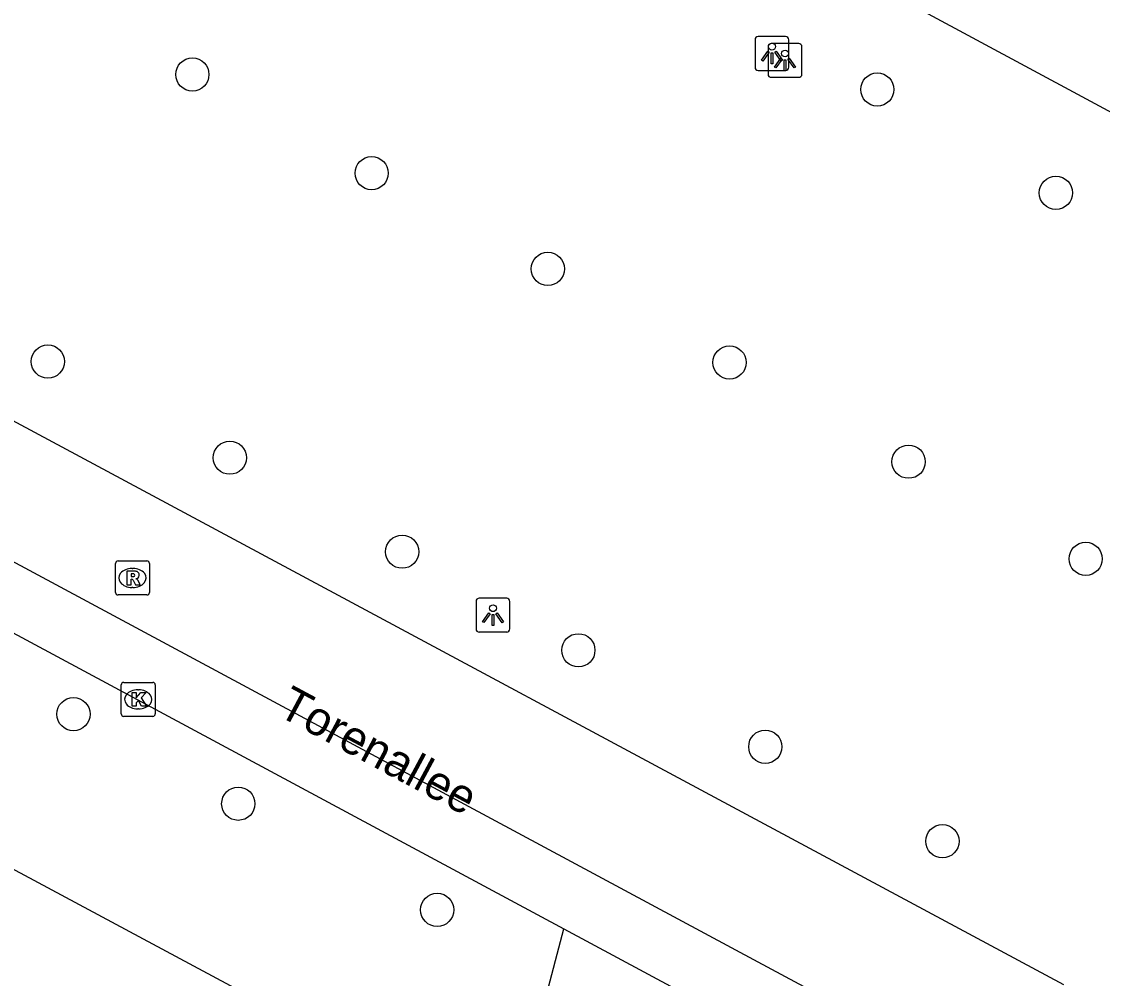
# Model space of a CAD drawing. Extents: x 159489 to 160304, y 383826 to 384530.
# Drawn here: x 159824.86 to 159856.68, y 384144.76 to 384172.94 of the extents above; entities that cross this region are included whole.
import ezdxf

# ---------------------------------------------------------------- set-up
doc = ezdxf.new("R2010")
doc.units = 0
for name, color, linetype in [('IMGEO_Boom', 7, 'Continuous'), ('IMGEO_Kolk', 7, 'Continuous'), ('IMGEO_Lichtpunt', 7, 'Continuous'), ('IMGEO_Openbare_ruimte_label', 7, 'Continuous'), ('IMGEO_Pand', 7, 'Continuous'), ('IMGEO_Rijbaan_lokaal_gesloten', 7, 'Continuous'), ('IMGEO_Rioolput', 7, 'Continuous'), ('IMGEO_Voetgangersgebied_gesloten', 7, 'Continuous'), ('IMGEO_Voetpad_open', 7, 'Continuous')]:
    doc.layers.add(name, color=color, linetype=linetype)

msp = doc.modelspace()

# ---------------------------------------------------------------- linework, layer by layer
at = {"layer": 'IMGEO_Boom'}
for centre in [(159829.887, 384171.386), (159850.05, 384170.943), (159835.164, 384168.48), (159855.308, 384167.898), (159840.349, 384165.658), (159825.633, 384162.929), (159845.701, 384162.903), (159830.989, 384160.097), (159850.971, 384159.979), (159836.063, 384157.328), (159856.184, 384157.117), (159841.25, 384154.425), (159826.385, 384152.545), (159846.752, 384151.583), (159831.238, 384149.905), (159851.966, 384148.8), (159837.094, 384146.777)]:
    msp.add_circle(centre, 0.489, dxfattribs=at)
at = {"layer": 'IMGEO_Kolk'}
for p, q in [((159827.792, 384152.553), (159827.792, 384153.405)), ((159827.867, 384153.479), (159828.719, 384153.479)), ((159828.28, 384153.259), (159828.305, 384153.259)), ((159828.793, 384153.405), (159828.793, 384152.553)), ((159828.303, 384152.699), (159828.278, 384152.699)), ((159828.719, 384152.479), (159827.867, 384152.479))]:
    msp.add_line(p, q, dxfattribs=at)
for points in [[(159827.792, 384152.553), (159827.792, 384153.405)], [(159827.867, 384153.479), (159828.719, 384153.479)], [(159828.793, 384153.405), (159828.793, 384152.553)], [(159828.113, 384153.179), (159828.236, 384153.179), (159828.236, 384153.028), (159828.366, 384153.179), (159828.53, 384153.179), (159828.384, 384153.028), (159828.537, 384152.779), (159828.385, 384152.779), (159828.3, 384152.943), (159828.236, 384152.876), (159828.236, 384152.779), (159828.113, 384152.779), (159828.113, 384153.179)], [(159828.719, 384152.479), (159827.867, 384152.479)]]:
    msp.add_lwpolyline(points, dxfattribs=at)
for centre, start, end in [((159827.869, 384153.403), 91.552, 178.448), ((159827.869, 384153.403), 91.552, 178.448), ((159828.717, 384153.403), 1.552, 88.448), ((159828.717, 384153.403), 1.552, 88.448), ((159827.869, 384152.555), 181.552, 268.448), ((159827.869, 384152.555), 181.552, 268.448), ((159828.717, 384152.555), 271.552, 358.448), ((159828.717, 384152.555), 271.552, 358.448)]:
    msp.add_arc(centre, 0.0765, start, end, dxfattribs=at)
for centre, major_axis, ratio, start_param, end_param in [((159828.279, 384152.979), (-0.387, 0.002), 0.722429, 4.712389, 7.853982), ((159828.304, 384152.979), (-0.39, 0.002), 0.717154, 1.570796, 4.712389)]:
    msp.add_ellipse(centre, major_axis=major_axis, ratio=ratio, start_param=start_param, end_param=end_param, dxfattribs=at)
at = {"layer": 'IMGEO_Lichtpunt'}
for p, q in [((159846.45, 384172.408), (159846.45, 384171.601)), ((159846.45, 384172.408), (159846.45, 384171.601)), ((159847.352, 384172.503), (159846.544, 384172.503)), ((159847.352, 384172.503), (159846.544, 384172.503)), ((159847.736, 384172.299), (159846.928, 384172.299)), ((159847.736, 384172.299), (159846.928, 384172.299)), ((159847.446, 384171.601), (159847.446, 384172.408)), ((159847.446, 384171.601), (159847.446, 384172.408)), ((159846.834, 384172.204), (159846.834, 384171.397)), ((159846.834, 384172.204), (159846.834, 384171.397)), ((159847.83, 384171.397), (159847.83, 384172.204)), ((159847.83, 384171.397), (159847.83, 384172.204)), ((159846.544, 384171.507), (159847.352, 384171.507)), ((159846.544, 384171.507), (159847.352, 384171.507)), ((159846.928, 384171.303), (159847.736, 384171.303)), ((159846.928, 384171.303), (159847.736, 384171.303)), ((159838.238, 384155.865), (159838.238, 384155.058)), ((159838.238, 384155.865), (159838.238, 384155.058)), ((159839.14, 384155.96), (159838.332, 384155.96)), ((159839.14, 384155.96), (159838.332, 384155.96)), ((159839.234, 384155.058), (159839.234, 384155.865)), ((159839.234, 384155.058), (159839.234, 384155.865)), ((159838.332, 384154.964), (159839.14, 384154.964)), ((159838.332, 384154.964), (159839.14, 384154.964))]:
    msp.add_line(p, q, dxfattribs=at)
for points in [[(159846.824, 384172.072), (159846.863, 384172.044), (159846.675, 384171.782), (159846.637, 384171.809), (159846.824, 384172.072)], [(159846.926, 384172.024), (159846.973, 384172.024), (159846.973, 384171.702), (159846.926, 384171.702), (159846.926, 384172.024)], [(159847.036, 384172.044), (159847.074, 384172.071), (159847.261, 384171.809), (159847.222, 384171.781), (159847.036, 384172.044)], [(159847.208, 384171.868), (159847.247, 384171.84), (159847.059, 384171.578), (159847.021, 384171.605), (159847.208, 384171.868)], [(159847.31, 384171.82), (159847.357, 384171.82), (159847.357, 384171.498), (159847.31, 384171.498), (159847.31, 384171.82)], [(159847.42, 384171.84), (159847.458, 384171.867), (159847.645, 384171.605), (159847.606, 384171.577), (159847.42, 384171.84)], [(159838.612, 384155.529), (159838.651, 384155.501), (159838.463, 384155.239), (159838.425, 384155.266), (159838.612, 384155.529)], [(159838.714, 384155.481), (159838.761, 384155.481), (159838.761, 384155.159), (159838.714, 384155.159), (159838.714, 384155.481)], [(159838.824, 384155.501), (159838.862, 384155.528), (159839.049, 384155.266), (159839.01, 384155.238), (159838.824, 384155.501)]]:
    msp.add_lwpolyline(points, dxfattribs=at)
for centre in [(159846.949, 384172.206), (159847.333, 384172.002), (159838.737, 384155.663)]:
    msp.add_circle(centre, 0.0994, dxfattribs=at)
for centre, start, end in [((159846.544, 384172.408), 90, 180), ((159846.544, 384172.408), 90, 180), ((159846.928, 384172.204), 90, 180), ((159846.928, 384172.204), 90, 180), ((159847.352, 384172.408), 0, 90), ((159847.352, 384172.408), 0, 90), ((159847.736, 384172.204), 0, 90), ((159847.736, 384172.204), 0, 90), ((159846.544, 384171.601), 180, 270), ((159846.544, 384171.601), 180, 270), ((159846.928, 384171.397), 180, 270), ((159846.928, 384171.397), 180, 270), ((159847.352, 384171.601), 270, 0), ((159847.352, 384171.601), 270, 360), ((159847.736, 384171.397), 270, 0), ((159847.736, 384171.397), 270, 360), ((159838.332, 384155.865), 90, 180), ((159838.332, 384155.865), 90, 180), ((159839.14, 384155.865), 0, 90), ((159839.14, 384155.865), 0, 90), ((159838.332, 384155.058), 180, 270), ((159838.332, 384155.058), 180, 270), ((159839.14, 384155.058), 270, 0), ((159839.14, 384155.058), 270, 360)]:
    msp.add_arc(centre, 0.0946, start, end, dxfattribs=at)
at = {"layer": 'IMGEO_Pand'}
msp.add_lwpolyline([(159839.222, 384140.129), (159819.699, 384150.609), (159819.305, 384150.823), (159814.929, 384153.207), (159799.236, 384161.615), (159795.062, 384163.855)], dxfattribs=at)
at = {"layer": 'IMGEO_Rijbaan_lokaal_gesloten'}
for points in [[(159855.536, 384144.567), (159759.321, 384196.257)], [(159802.216, 384166.981), (159803.09, 384168.608), (159846.53, 384145.249), (159851.528, 384142.567), (159850.655, 384140.94)]]:
    msp.add_lwpolyline(points, dxfattribs=at)
at = {"layer": 'IMGEO_Rioolput'}
for p, q in [((159827.698, 384157.056), (159828.55, 384157.056)), ((159827.623, 384156.13), (159827.623, 384156.982)), ((159828.111, 384156.836), (159828.136, 384156.836)), ((159828.624, 384156.982), (159828.624, 384156.13)), ((159828.55, 384156.056), (159827.698, 384156.056)), ((159828.134, 384156.276), (159828.109, 384156.276))]:
    msp.add_line(p, q, dxfattribs=at)
for points in [[(159827.698, 384157.056), (159828.55, 384157.056)], [(159827.623, 384156.13), (159827.623, 384156.982)], [(159828.212, 384156.754), (159827.96, 384156.756), (159827.96, 384156.356)], [(159828.624, 384156.982), (159828.624, 384156.13)], [(159827.96, 384156.356), (159828.084, 384156.356), (159828.084, 384156.518), (159828.095, 384156.518)], [(159828.138, 384156.675), (159828.084, 384156.675), (159828.084, 384156.594)], [(159828.084, 384156.594), (159828.136, 384156.594)], [(159828.142, 384156.489), (159828.213, 384156.356), (159828.353, 384156.356), (159828.288, 384156.482)], [(159828.55, 384156.056), (159827.698, 384156.056)]]:
    msp.add_lwpolyline(points, dxfattribs=at)
for centre, radius, start, end in [((159827.7, 384156.98), 0.0765, 91.552, 178.448), ((159827.7, 384156.98), 0.0765, 91.552, 178.448), ((159828.548, 384156.98), 0.0765, 1.552, 88.448), ((159828.548, 384156.98), 0.0765, 1.552, 88.448), ((159828.211, 384156.644), 0.109, 350.3612, 89.416), ((159828.094, 384156.465), 0.0533, 26.0293, 88.6989), ((159828.12, 384156.783), 0.19, 274.7715, 282.9687), ((159828.144, 384156.579), 0.0964, 77.0061, 93.1865), ((159828.158, 384156.636), 0.0378, 276.6634, 79.6772), ((159828.209, 384156.644), 0.112, 277.5842, 350.9817), ((159828.193, 384156.429), 0.108, 29.5134, 73.7905), ((159827.7, 384156.132), 0.0765, 181.552, 268.448), ((159827.7, 384156.132), 0.0765, 181.552, 268.448), ((159828.548, 384156.132), 0.0765, 271.552, 358.448), ((159828.548, 384156.132), 0.0765, 271.552, 358.448)]:
    msp.add_arc(centre, radius, start, end, dxfattribs=at)
for centre, major_axis, ratio, start_param, end_param in [((159828.11, 384156.556), (-0.387, 0.002), 0.722429, 4.712389, 7.853982), ((159828.135, 384156.556), (-0.39, 0.002), 0.717154, 1.570796, 4.712389)]:
    msp.add_ellipse(centre, major_axis=major_axis, ratio=ratio, start_param=start_param, end_param=end_param, dxfattribs=at)
at = {"layer": 'IMGEO_Voetgangersgebied_gesloten'}
msp.add_lwpolyline([(159828.032, 384185.836), (159873.122, 384161.552)], dxfattribs=at)
at = {"layer": 'IMGEO_Voetpad_open'}
for points in [[(159802.216, 384166.981), (159840.824, 384146.221)], [(159839.222, 384140.129), (159840.824, 384146.221)], [(159840.824, 384146.221), (159845.656, 384143.622), (159850.655, 384140.94)]]:
    msp.add_lwpolyline(points, dxfattribs=at)

# ---------------------------------------------------------------- texts
at = {"layer": 'IMGEO_Openbare_ruimte_label'}
msp.add_text('Torenallee', height=1, rotation=331.7691, dxfattribs=at).set_placement((159832.351, 384152.53))

doc.saveas('drawing.dxf')
